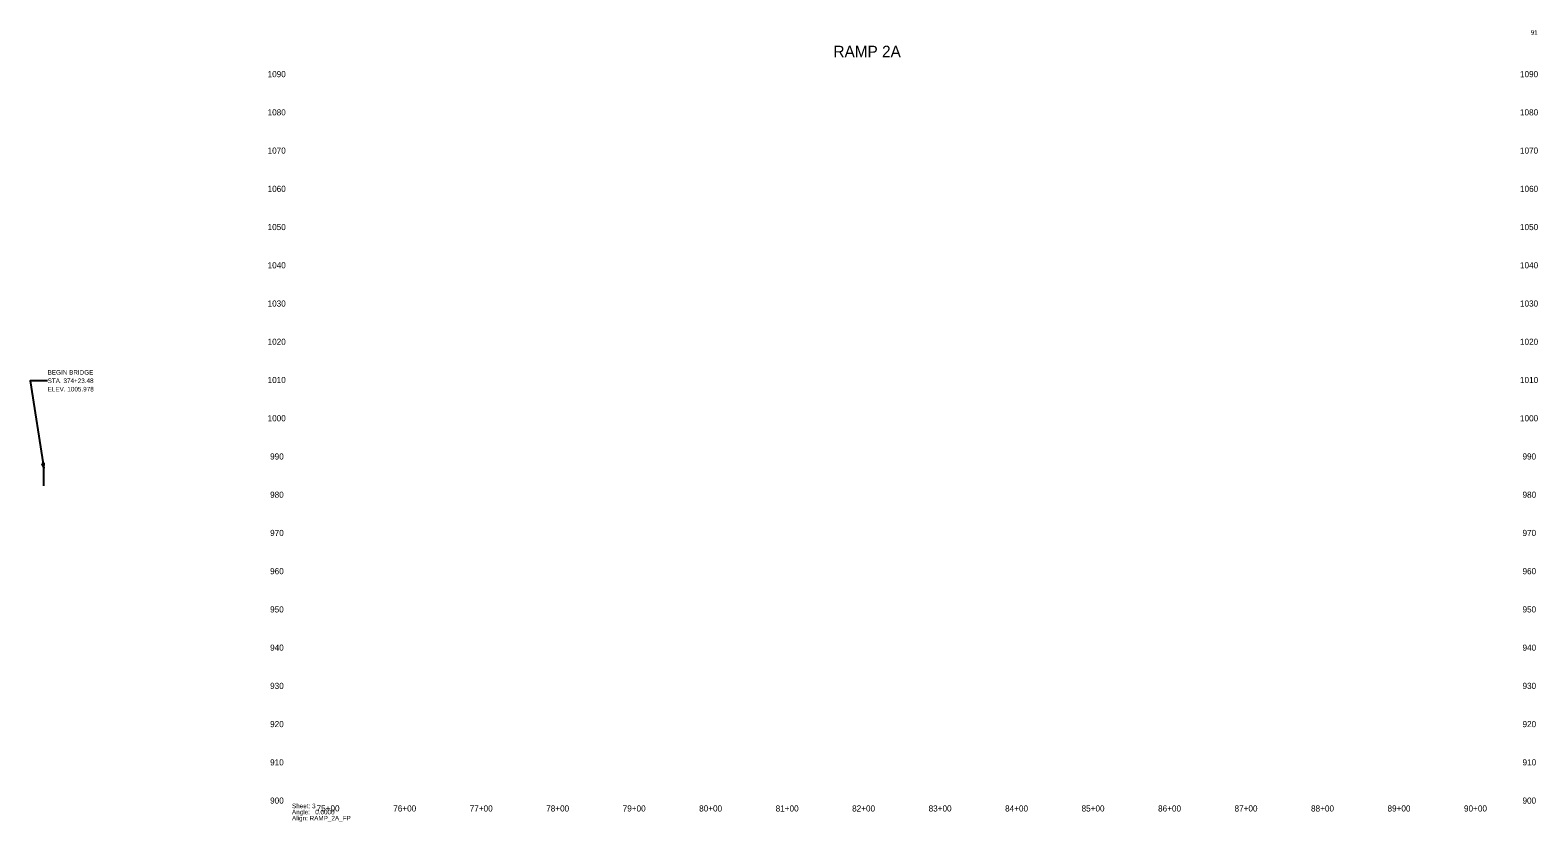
# Model space of a CAD drawing. Extents: x 16975588 to 16977559, y 12564064 to 12565099.
import ezdxf

# ---------------------------------------------------------------- set-up
doc = ezdxf.new("R2010")
doc.units = 0
for name, color, linetype in [('Default', 7, 'Continuous'), ('RD_DDB_ElevTX', 7, 'Continuous'), ('RD_DDB_StaTX', 7, 'Continuous'), ('RD_PD_Bridge', 7, 'Continuous'), ('RD_SHT_TX', 7, 'Continuous')]:
    doc.layers.add(name, color=color, linetype=linetype)

msp = doc.modelspace()

# ---------------------------------------------------------------- linework, layer by layer
at = {"layer": 'RD_PD_Bridge'}
msp.add_line((16975605.5, 12564503.2), (16975605.5, 12564526.6), dxfattribs=at)
at = {"layer": 'RD_SHT_TX'}
msp.add_lwpolyline([(16975610.5, 12564640.8), (16975587.7, 12564640.8), (16975605.5, 12564526.6)], dxfattribs=at)
msp.add_lwpolyline([(16975603, 12564532.1), (16975605.5, 12564526.6), (16975606.1, 12564532.5)], close=True, dxfattribs=at)

# ---------------------------------------------------------------- texts
at = {"layer": 'Default'}
for s, p in [('Sheet: 3', (16975930, 12564081.8)), ('Angle:   0.0000', (16975930, 12564073.8)), ('Align: RAMP_2A_FP', (16975930, 12564065.8))]:
    msp.add_text(s, height=6, dxfattribs=at).set_placement(p)
at = {"layer": 'RD_DDB_ElevTX'}
for s, p in [('1090', (16975898.1, 12565037.8)), ('1090', (16977535.6, 12565037.8)), ('1080', (16975898.1, 12564987.8)), ('1080', (16977535.6, 12564987.8)), ('1070', (16975898.1, 12564937.8)), ('1070', (16977535.6, 12564937.8)), ('1060', (16975898.1, 12564887.8)), ('1060', (16977535.6, 12564887.8)), ('1050', (16975898.1, 12564837.8)), ('1050', (16977535.6, 12564837.8)), ('1040', (16975898.1, 12564787.8)), ('1040', (16977535.6, 12564787.8)), ('1030', (16975898.1, 12564737.8)), ('1030', (16977535.6, 12564737.8)), ('1020', (16975898.1, 12564687.8)), ('1020', (16977535.6, 12564687.8)), ('1010', (16975898.1, 12564637.8)), ('1010', (16977535.6, 12564637.8)), ('1000', (16975898.1, 12564587.8)), ('1000', (16977535.6, 12564587.8)), ('990', (16975901.4, 12564537.8)), ('990', (16977538.9, 12564537.8)), ('980', (16975901.4, 12564487.8)), ('980', (16977538.9, 12564487.8)), ('970', (16975901.4, 12564437.8)), ('970', (16977538.9, 12564437.8)), ('960', (16975901.4, 12564387.8)), ('960', (16977538.9, 12564387.8)), ('950', (16975901.4, 12564337.8)), ('950', (16977538.9, 12564337.8)), ('940', (16975901.4, 12564287.8)), ('940', (16977538.9, 12564287.8)), ('930', (16975901.4, 12564237.8)), ('930', (16977538.9, 12564237.8)), ('920', (16975901.4, 12564187.8)), ('920', (16977538.9, 12564187.8)), ('910', (16975901.4, 12564137.8)), ('910', (16977538.9, 12564137.8)), ('900', (16975901.4, 12564087.8)), ('900', (16977538.9, 12564087.8))]:
    msp.add_text(s, height=8, dxfattribs=at).set_placement(p)
at = {"layer": 'RD_DDB_StaTX'}
for s, p in [('75+00', (16975962.2, 12564077.6)), ('76+00', (16976062.4, 12564077.5)), ('77+00', (16976162.4, 12564077.5)), ('78+00', (16976262.4, 12564077.5)), ('79+00', (16976362.4, 12564077.5)), ('80+00', (16976462.4, 12564077.5)), ('81+00', (16976562.4, 12564077.5)), ('82+00', (16976662.4, 12564077.5)), ('83+00', (16976762.4, 12564077.5)), ('84+00', (16976862.4, 12564077.5)), ('85+00', (16976962.4, 12564077.5)), ('86+00', (16977062.4, 12564077.5)), ('87+00', (16977162.4, 12564077.5)), ('88+00', (16977262.4, 12564077.5)), ('89+00', (16977362.4, 12564077.5)), ('90+00', (16977462.4, 12564077.5))]:
    msp.add_text(s, height=8, dxfattribs=at).set_placement(p)
at = {"layer": 'RD_SHT_TX'}
for s, height, p in [('91', 6, (16977549.6, 12565093.2)), ('RAMP 2A', 15, (16976638, 12565063.9))]:
    msp.add_text(s, height=height, dxfattribs=at).set_placement(p)
for s, p in [('BEGIN BRIDGE', (16975610.5, 12564648.8)), ('STA. 374+23.48', (16975610.5, 12564637.8)), ('ELEV. 1005.978', (16975610.5, 12564626.8))]:
    msp.add_text(s, height=6, rotation=360, dxfattribs=at).set_placement(p)

doc.saveas('drawing.dxf')
